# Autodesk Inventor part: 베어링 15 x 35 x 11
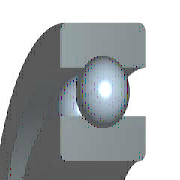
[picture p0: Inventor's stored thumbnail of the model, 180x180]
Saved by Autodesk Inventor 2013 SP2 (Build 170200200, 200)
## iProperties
Created: 2012-02
Part Number: 베어링 15 x 35 x 11
Material: 강철, 연강
Description: 깊은 그루브 볼 베어링
Document SubType Name: Modeling
Standard: KS B 2023
Designer: mduedu
Standards Organization: KS
Language: ko-KR
Size Designation: 6202 - 15 x 35 x 11
Categories: <MemberInstance><Categories><Category DisplayName="샤프트 부품" InternalName="7f7aeb1f-a693-4053-b835-cee3144e0d98" Mnemonic="SHFT"><Category DisplayName="베어링" Inter
Density: 1 g/cm^3
IsCustomPart: 1
Author: mduedu
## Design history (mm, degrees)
sketch "스케치" dims "d0" = 5.2 (= -0.26 x WD + 0.26 x BD)
  geometry: L1 (2.9, 12.5)-(8.1, 12.5); L2 (5.5, 12.5)-(5.5, 9.9); L3 (5.5, 12.5)-(5.5, 15.1); L4 (3.568, 10.76)-(0, 10.76); L5 (0, 7.5)-(11, 7.5); L6 (3.568, 14.24)-(0, 14.24); L7 (0, 17.5)-(11, 17.5); L8 (11, 7.5)-(11, 10.76); L9 (7.432, 10.76)-(11, 10.76); L10 (7.432, 14.24)-(11, 14.24); L11 (11, 17.5)-(11, 14.24); L12 (-1.4, 0)-(8.4, 0) reference; L13 (0, -0.3)-(0, 5.3) reference
  constraints: 22 end point, 4 point on line, 2 collinear, 2 perpendicular, 2 symmetric about line, 1 midpoint, 1 parallel, 14 other
  dimensions: "d9" = 15 diameter of L5 L12 (= WD); "d11" = 35 diameter of L7 L12 (= BD); "d12" = 11 distance between parallel lines of L8 L13 (= KB); "d13" = 21.52 diameter of L9 L12 (= 0.326 x BD + 0.674 x WD)
revolve "본체" stored, may be unused: angle "d6" = 90 deg
revolve "볼" stored, may be unused: angle "d7" = 90 deg
pattern_circular "IDS_ARRAYBALL[SIMPL:T]" dims angle "d3" = 360 deg
body "Solid1"
fillet "모깎기1" dims "d1" = 0.6 (= KRS)
other parameters: "WD" = 15 [user parameter; used in 5 equation terms], "BD" = 35 [user parameter; used in 5 equation terms], "KB" = 11 [user parameter; used in 1 equation term], "KRS" = 0.6 [user parameter; used in 1 equation term], "d4" = 0, "d5" = 0, "d8" = 0, "d14" = 0, "d15" = 0, "BBA" = 0 [user parameter], "BC0" = 3750000 [user parameter], "BC" = 7800000 [user parameter], "BR" = 17.5 (= 0.5 x BD) [user parameter], "WR" = 7.5 (= 0.5 x WD) [user parameter]
